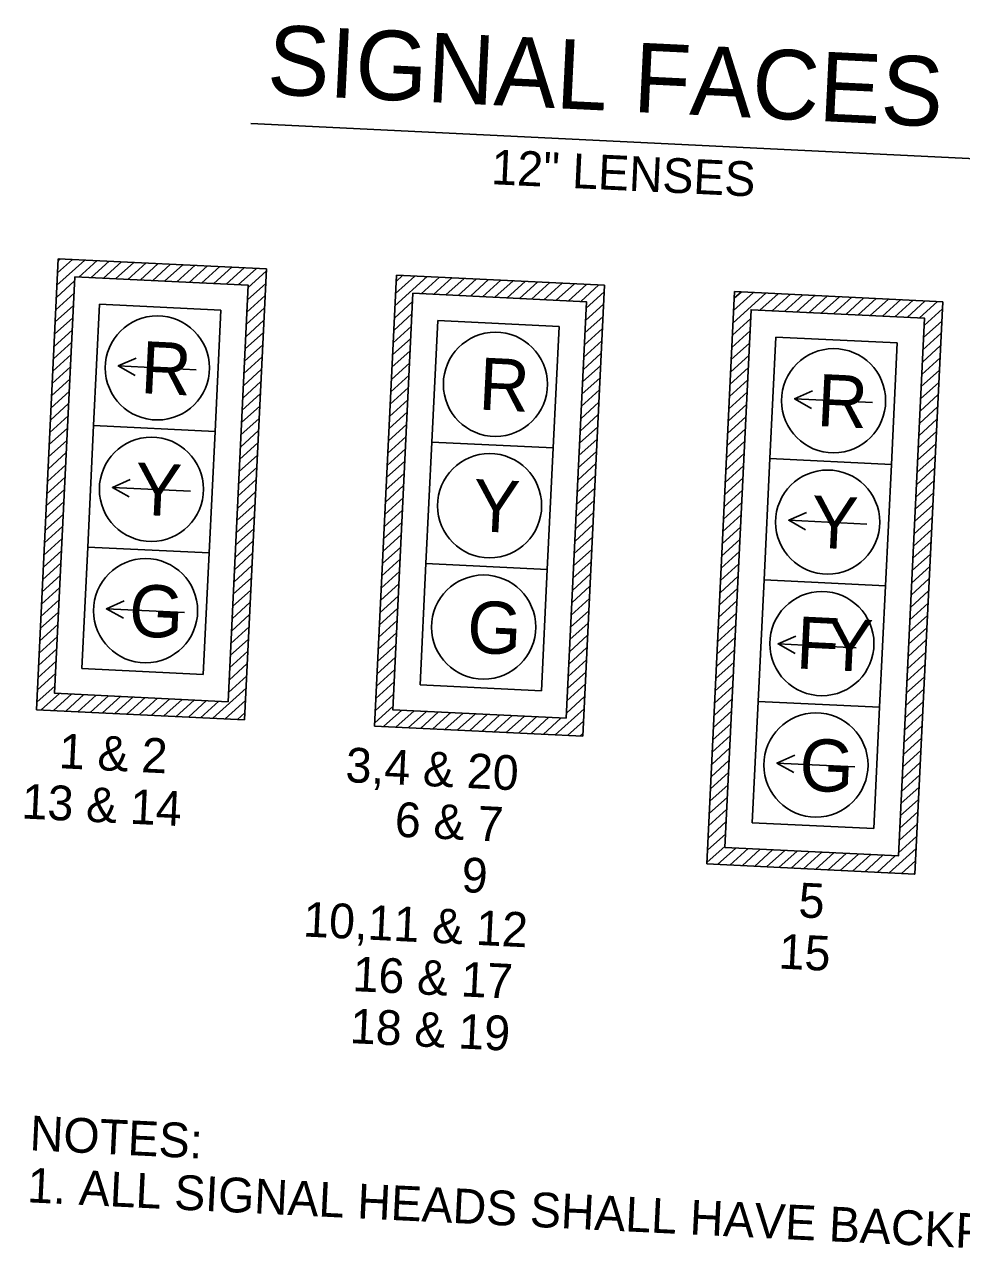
# Model space of a CAD drawing. Extents: x 662220 to 671027, y 641390 to 743815.
# Drawn here: x 662467.9 to 662575.9, y 642595.1 to 642736.9 of the extents above; entities that cross this region are included whole.
import ezdxf

# ---------------------------------------------------------------- set-up
doc = ezdxf.new("R2010")
doc.units = 0
doc.layers.add('R_Proposed Road Annot', color=7, linetype='Continuous')

msp = doc.modelspace()

# ---------------------------------------------------------------- linework, layer by layer
at = {"layer": 'R_Proposed Road Annot'}
for p, q in [((662494.01, 642725.55), (662592.08, 642720.79)), ((662469.3, 642658.04), (662471.82, 642709.98)), ((662471.67, 642706.94), (662474.87, 642709.83)), ((662471.74, 642708.35), (662473.46, 642709.9)), ((662471.81, 642709.76), (662472.04, 642709.97)), ((662471.82, 642709.98), (662495.79, 642708.82)), ((662474.19, 642707.86), (662476.28, 642709.77)), ((662475.6, 642707.8), (662477.69, 642709.7)), ((662477.01, 642707.73), (662479.11, 642709.63)), ((662478.42, 642707.66), (662480.52, 642709.56)), ((662479.84, 642707.59), (662481.93, 642709.49)), ((662481.25, 642707.52), (662483.34, 642709.42)), ((662482.66, 642707.45), (662484.76, 642709.35)), ((662484.07, 642707.38), (662486.17, 642709.28)), ((662485.49, 642707.32), (662487.58, 642709.22)), ((662486.9, 642707.25), (662488.99, 642709.15)), ((662488.31, 642707.18), (662490.41, 642709.08)), ((662489.72, 642707.11), (662491.82, 642709.01)), ((662491.14, 642707.04), (662493.23, 642708.94)), ((662492.55, 642706.97), (662494.64, 642708.87)), ((662495.79, 642708.82), (662493.27, 642656.88)), ((662493.69, 642706.65), (662495.78, 642708.55)), ((662510.78, 642708.09), (662508.25, 642656.15)), ((662510.6, 642704.55), (662514.32, 642707.92)), ((662510.67, 642705.96), (662512.91, 642707.99)), ((662510.74, 642707.37), (662511.49, 642708.06)), ((662534.75, 642706.93), (662510.78, 642708.09)), ((662513.64, 642705.95), (662515.73, 642707.85)), ((662515.05, 642705.88), (662517.14, 642707.78)), ((662516.46, 642705.81), (662518.56, 642707.71)), ((662471.61, 642705.52), (662473.7, 642707.42)), ((662493.62, 642705.24), (662495.71, 642707.14)), ((662517.87, 642705.74), (662519.97, 642707.64)), ((662519.29, 642705.67), (662521.38, 642707.58)), ((662520.7, 642705.61), (662522.79, 642707.51)), ((662522.11, 642705.54), (662524.21, 642707.44)), ((662523.52, 642705.47), (662525.62, 642707.37)), ((662524.94, 642705.4), (662527.03, 642707.3)), ((662526.35, 642705.33), (662528.44, 642707.23)), ((662527.76, 642705.26), (662529.86, 642707.16)), ((662529.17, 642705.19), (662531.27, 642707.09)), ((662530.59, 642705.13), (662532.68, 642707.03)), ((662532, 642705.06), (662534.09, 642706.96)), ((662532.23, 642654.99), (662534.75, 642706.93)), ((662471.54, 642704.11), (662473.63, 642706.01)), ((662493.55, 642703.83), (662495.64, 642705.73)), ((662510.54, 642703.13), (662512.63, 642705.04)), ((662532.62, 642704.27), (662534.71, 642706.17)), ((662546.53, 642640.28), (662549.73, 642706.2)), ((662549.55, 642702.6), (662553.33, 642706.02)), ((662549.62, 642704.01), (662551.92, 642706.09)), ((662549.69, 642705.42), (662550.51, 642706.16)), ((662549.73, 642706.2), (662573.7, 642705.03)), ((662552.65, 642704.05), (662554.75, 642705.95)), ((662554.06, 642703.99), (662556.16, 642705.89)), ((662555.48, 642703.92), (662557.57, 642705.82)), ((662556.89, 642703.85), (662558.98, 642705.75)), ((662558.3, 642703.78), (662560.4, 642705.68)), ((662559.71, 642703.71), (662561.81, 642705.61)), ((662561.13, 642703.64), (662563.22, 642705.54)), ((662562.54, 642703.57), (662564.63, 642705.47)), ((662563.95, 642703.51), (662566.05, 642705.41)), ((662565.36, 642703.44), (662567.46, 642705.34)), ((662566.78, 642703.37), (662568.87, 642705.27)), ((662568.19, 642703.3), (662570.28, 642705.2)), ((662569.6, 642703.23), (662571.7, 642705.13)), ((662573.7, 642705.03), (662570.5, 642639.11)), ((662571.01, 642703.16), (662573.11, 642705.06)), ((662471.47, 642702.7), (662473.56, 642704.6)), ((662476.57, 642704.75), (662475.89, 642690.76)), ((662476.57, 642704.75), (662490.56, 642704.07)), ((662490.56, 642704.07), (662489.88, 642690.08)), ((662493.48, 642702.42), (662495.57, 642704.32)), ((662510.47, 642701.72), (662512.56, 642703.62)), ((662532.55, 642702.85), (662534.64, 642704.75)), ((662571.57, 642702.31), (662573.66, 642704.22)), ((662471.4, 642701.29), (662473.49, 642703.19)), ((662493.41, 642701), (662495.51, 642702.9)), ((662510.4, 642700.31), (662512.49, 642702.21)), ((662515.53, 642702.85), (662514.85, 642688.87)), ((662515.53, 642702.85), (662529.51, 642702.17)), ((662529.51, 642702.17), (662528.83, 642688.19)), ((662532.48, 642701.44), (662534.57, 642703.34)), ((662549.49, 642701.18), (662551.58, 642703.08)), ((662571.5, 642700.9), (662573.59, 642702.8)), ((662471.33, 642699.87), (662473.43, 642701.77)), ((662493.34, 642699.59), (662495.44, 642701.49)), ((662510.33, 642698.9), (662512.42, 642700.8)), ((662532.41, 642700.03), (662534.5, 642701.93)), ((662549.42, 642699.77), (662551.51, 642701.67)), ((662554.48, 642700.96), (662553.8, 642686.98)), ((662554.48, 642700.96), (662568.46, 642700.28)), ((662571.43, 642699.49), (662573.52, 642701.39)), ((662471.26, 642698.46), (662473.36, 642700.36)), ((662493.27, 642698.18), (662495.37, 642700.08)), ((662510.26, 642697.48), (662512.36, 642699.39)), ((662532.34, 642698.62), (662534.44, 642700.52)), ((662549.35, 642698.36), (662551.44, 642700.26)), ((662568.46, 642700.28), (662567.79, 642686.3)), ((662571.36, 642698.08), (662573.46, 642699.98)), ((662471.19, 642697.05), (662473.29, 642698.95)), ((662493.21, 642696.77), (662495.3, 642698.67)), ((662510.19, 642696.07), (662512.29, 642697.97)), ((662532.27, 642697.2), (662534.37, 642699.1)), ((662549.28, 642696.95), (662551.38, 642698.85)), ((662571.29, 642696.66), (662573.39, 642698.56)), ((662471.12, 642695.63), (662473.22, 642697.54)), ((662487.72, 642697.2), (662478.73, 642697.63)), ((662493.14, 642695.35), (662495.23, 642697.25)), ((662510.12, 642694.66), (662512.22, 642696.56)), ((662532.2, 642695.79), (662534.3, 642697.69)), ((662549.21, 642695.53), (662551.31, 642697.43)), ((662571.22, 642695.25), (662573.32, 642697.15)), ((662471.06, 642694.22), (662473.15, 642696.12)), ((662493.07, 642693.94), (662495.16, 642695.84)), ((662510.05, 642693.25), (662512.15, 642695.15)), ((662532.14, 642694.38), (662534.23, 642696.28)), ((662549.14, 642694.12), (662551.24, 642696.02)), ((662571.16, 642693.84), (662573.25, 642695.74)), ((662470.99, 642692.81), (662473.08, 642694.71)), ((662493, 642692.53), (662495.09, 642694.43)), ((662509.99, 642691.83), (662512.08, 642693.74)), ((662532.07, 642692.97), (662534.16, 642694.87)), ((662549.07, 642692.71), (662551.17, 642694.61)), ((662565.63, 642693.41), (662556.64, 642693.85)), ((662571.09, 642692.43), (662573.18, 642694.33)), ((662470.92, 642691.4), (662473.01, 642693.3)), ((662492.93, 642691.12), (662495.03, 642693.02)), ((662509.92, 642690.42), (662512.01, 642692.32)), ((662532, 642691.55), (662534.09, 642693.45)), ((662549.01, 642691.3), (662551.1, 642693.2)), ((662571.02, 642691.01), (662573.11, 642692.91)), ((662470.85, 642689.98), (662472.95, 642691.89)), ((662475.89, 642690.76), (662475.22, 642676.78)), ((662475.89, 642690.76), (662489.88, 642690.08)), ((662492.86, 642689.7), (662494.96, 642691.6)), ((662509.85, 642689.01), (662511.94, 642690.91)), ((662531.93, 642690.14), (662534.02, 642692.04)), ((662548.94, 642689.88), (662551.03, 642691.78)), ((662570.95, 642689.6), (662573.04, 642691.5)), ((662470.78, 642688.57), (662472.88, 642690.47)), ((662489.88, 642690.08), (662489.2, 642676.1)), ((662492.79, 642688.29), (662494.89, 642690.19)), ((662509.78, 642687.6), (662511.88, 642689.5)), ((662531.86, 642688.73), (662533.96, 642690.63)), ((662548.87, 642688.47), (662550.96, 642690.37)), ((662570.88, 642688.19), (662572.98, 642690.09)), ((662470.71, 642687.16), (662472.81, 642689.06)), ((662492.73, 642686.88), (662494.82, 642688.78)), ((662509.71, 642686.18), (662511.81, 642688.08)), ((662514.85, 642688.87), (662514.17, 642674.89)), ((662514.85, 642688.87), (662528.83, 642688.19)), ((662528.83, 642688.19), (662528.15, 642674.21)), ((662531.79, 642687.32), (662533.89, 642689.22)), ((662548.8, 642687.06), (662550.89, 642688.96)), ((662570.81, 642686.78), (662572.91, 642688.68)), ((662470.64, 642685.75), (662472.74, 642687.65)), ((662492.66, 642685.47), (662494.75, 642687.37)), ((662509.64, 642684.77), (662511.74, 642686.67)), ((662531.72, 642685.9), (662533.82, 642687.8)), ((662548.73, 642685.65), (662550.83, 642687.55)), ((662553.8, 642686.98), (662553.12, 642672.99)), ((662553.8, 642686.98), (662567.79, 642686.3)), ((662570.74, 642685.36), (662572.84, 642687.26)), ((662470.58, 642684.33), (662472.67, 642686.24)), ((662492.59, 642684.05), (662494.68, 642685.95)), ((662509.57, 642683.36), (662511.67, 642685.26)), ((662531.66, 642684.49), (662533.75, 642686.39)), ((662548.66, 642684.23), (662550.76, 642686.13)), ((662567.79, 642686.3), (662567.11, 642672.32)), ((662570.68, 642683.95), (662572.77, 642685.85)), ((662470.51, 642682.92), (662472.6, 642684.82)), ((662487.04, 642683.21), (662478.05, 642683.65)), ((662492.52, 642682.64), (662494.61, 642684.54)), ((662509.51, 642681.95), (662511.6, 642683.85)), ((662531.59, 642683.08), (662533.68, 642684.98)), ((662548.59, 642682.82), (662550.69, 642684.72)), ((662570.61, 642682.54), (662572.7, 642684.44)), ((662470.44, 642681.51), (662472.53, 642683.41)), ((662492.45, 642681.23), (662494.55, 642683.13)), ((662509.44, 642680.53), (662511.53, 642682.43)), ((662531.52, 642681.67), (662533.61, 642683.57)), ((662548.53, 642681.41), (662550.62, 642683.31)), ((662570.54, 642681.13), (662572.63, 642683.03)), ((662470.37, 642680.1), (662472.47, 642682)), ((662492.38, 642679.82), (662494.48, 642681.72)), ((662509.37, 642679.12), (662511.46, 642681.02)), ((662531.45, 642680.25), (662533.54, 642682.15)), ((662548.46, 642679.99), (662550.55, 642681.9)), ((662570.47, 642679.71), (662572.56, 642681.61)), ((662470.3, 642678.68), (662472.4, 642680.58)), ((662492.31, 642678.4), (662494.41, 642680.3)), ((662509.3, 642677.71), (662511.4, 642679.61)), ((662531.38, 642678.84), (662533.48, 642680.74)), ((662548.39, 642678.58), (662550.48, 642680.48)), ((662564.95, 642679.43), (662555.96, 642679.87)), ((662570.4, 642678.3), (662572.5, 642680.2)), ((662470.23, 642677.27), (662472.33, 642679.17)), ((662492.25, 642676.99), (662494.34, 642678.89)), ((662509.23, 642676.3), (662511.33, 642678.2)), ((662531.31, 642677.43), (662533.41, 642679.33)), ((662548.32, 642677.17), (662550.41, 642679.07)), ((662570.33, 642676.89), (662572.43, 642678.79)), ((662470.16, 642675.86), (662472.26, 642677.76)), ((662475.22, 642676.78), (662474.54, 642662.79)), ((662475.22, 642676.78), (662489.2, 642676.1)), ((662492.18, 642675.58), (662494.27, 642677.48)), ((662509.16, 642674.88), (662511.26, 642676.78)), ((662531.18, 642674.6), (662533.27, 642676.5)), ((662531.24, 642676.02), (662533.34, 642677.92)), ((662548.25, 642675.76), (662550.35, 642677.66)), ((662570.26, 642675.48), (662572.36, 642677.38)), ((662470.1, 642674.45), (662472.19, 642676.35)), ((662489.2, 642676.1), (662488.52, 642662.12)), ((662492.11, 642674.17), (662494.2, 642676.07)), ((662509.09, 642673.47), (662511.19, 642675.37)), ((662531.11, 642673.19), (662533.2, 642675.09)), ((662548.18, 642674.34), (662550.28, 642676.25)), ((662570.2, 642674.06), (662572.29, 642675.96)), ((662470.03, 642673.03), (662472.12, 642674.93)), ((662492.04, 642672.75), (662494.13, 642674.65)), ((662509.03, 642672.06), (662511.12, 642673.96)), ((662514.17, 642674.89), (662513.49, 642660.9)), ((662514.17, 642674.89), (662528.15, 642674.21)), ((662528.15, 642674.21), (662527.47, 642660.22)), ((662531.04, 642671.78), (662533.13, 642673.68)), ((662548.11, 642672.93), (662550.21, 642674.83)), ((662570.13, 642672.65), (662572.22, 642674.55)), ((662469.96, 642671.62), (662472.05, 642673.52)), ((662491.97, 642671.34), (662494.07, 642673.24)), ((662508.96, 642670.65), (662511.05, 642672.55)), ((662530.97, 642670.37), (662533.06, 642672.27)), ((662548.05, 642671.52), (662550.14, 642673.42)), ((662553.12, 642672.99), (662552.44, 642659.01)), ((662553.12, 642672.99), (662567.11, 642672.32)), ((662567.11, 642672.32), (662566.43, 642658.33)), ((662570.06, 642671.24), (662572.15, 642673.14)), ((662469.89, 642670.21), (662471.98, 642672.11)), ((662491.9, 642669.93), (662494, 642671.83)), ((662508.89, 642669.23), (662510.98, 642671.13)), ((662530.9, 642668.95), (662533, 642670.85)), ((662547.98, 642670.11), (662550.07, 642672.01)), ((662569.99, 642669.83), (662572.08, 642671.73)), ((662469.82, 642668.8), (662471.92, 642670.7)), ((662486.36, 642669.23), (662477.37, 642669.66)), ((662491.83, 642668.52), (662493.93, 642670.42)), ((662508.82, 642667.82), (662510.91, 642669.72)), ((662530.83, 642667.54), (662532.93, 642669.44)), ((662547.91, 642668.69), (662550, 642670.6)), ((662569.92, 642668.41), (662572.02, 642670.31)), ((662469.75, 642667.38), (662471.85, 642669.28)), ((662491.77, 642667.1), (662493.86, 642669)), ((662508.75, 642666.41), (662510.85, 642668.31)), ((662530.76, 642666.13), (662532.86, 642668.03)), ((662547.84, 642667.28), (662549.93, 642669.18)), ((662569.85, 642667), (662571.95, 642668.9)), ((662469.68, 642665.97), (662471.78, 642667.87)), ((662491.7, 642665.69), (662493.79, 642667.59)), ((662508.68, 642665), (662510.78, 642666.9)), ((662530.7, 642664.71), (662532.79, 642666.62)), ((662547.77, 642665.87), (662549.87, 642667.77)), ((662569.78, 642665.59), (662571.88, 642667.49)), ((662469.62, 642664.56), (662471.71, 642666.46)), ((662491.63, 642664.28), (662493.72, 642666.18)), ((662508.61, 642663.58), (662510.71, 642665.48)), ((662530.63, 642663.3), (662532.72, 642665.2)), ((662547.7, 642664.46), (662549.8, 642666.36)), ((662563.73, 642665.19), (662554.74, 642665.63)), ((662569.72, 642664.18), (662571.81, 642666.08)), ((662469.55, 642663.15), (662471.64, 642665.05)), ((662491.56, 642662.87), (662493.65, 642664.77)), ((662508.55, 642662.17), (662510.64, 642664.07)), ((662530.56, 642661.89), (662532.65, 642663.79)), ((662547.63, 642663.04), (662549.73, 642664.94)), ((662569.65, 642662.76), (662571.74, 642664.66)), ((662469.48, 642661.73), (662471.57, 642663.63)), ((662474.54, 642662.79), (662488.52, 642662.12)), ((662491.49, 642661.45), (662493.59, 642663.35)), ((662508.48, 642660.76), (662510.57, 642662.66)), ((662530.49, 642660.48), (662532.58, 642662.38)), ((662547.57, 642661.63), (662549.66, 642663.53)), ((662569.58, 642661.35), (662571.67, 642663.25)), ((662469.41, 642660.32), (662471.5, 642662.22)), ((662491.42, 642660.04), (662493.52, 642661.94)), ((662508.41, 642659.35), (662510.5, 642661.25)), ((662513.49, 642660.9), (662527.47, 642660.22)), ((662530.42, 642659.06), (662532.52, 642660.97)), ((662547.5, 642660.22), (662549.59, 642662.12)), ((662569.51, 642659.94), (662571.6, 642661.84)), ((662469.34, 642658.91), (662471.44, 642660.81)), ((662469.85, 642658.02), (662471.94, 642659.92)), ((662471.26, 642657.95), (662473.35, 642659.85)), ((662472.67, 642657.88), (662474.77, 642659.78)), ((662474.08, 642657.81), (662476.18, 642659.71)), ((662475.5, 642657.74), (662477.59, 642659.64)), ((662476.91, 642657.67), (662479, 642659.57)), ((662478.32, 642657.6), (662480.42, 642659.51)), ((662489.62, 642657.06), (662493.45, 642660.53)), ((662508.34, 642657.93), (662510.43, 642659.83)), ((662530.35, 642657.65), (662532.45, 642659.55)), ((662547.43, 642658.81), (662549.52, 642660.71)), ((662569.44, 642658.53), (662571.54, 642660.43)), ((662479.73, 642657.54), (662481.83, 642659.44)), ((662481.15, 642657.47), (662483.24, 642659.37)), ((662482.56, 642657.4), (662484.65, 642659.3)), ((662483.97, 642657.33), (662486.07, 642659.23)), ((662485.38, 642657.26), (662487.48, 642659.16)), ((662486.8, 642657.19), (662488.89, 642659.09)), ((662488.21, 642657.12), (662490.3, 642659.03)), ((662491.03, 642656.99), (662493.38, 642659.12)), ((662508.27, 642656.52), (662510.37, 642658.42)), ((662529.07, 642655.14), (662532.38, 642658.14)), ((662547.36, 642657.39), (662549.45, 642659.29)), ((662552.44, 642659.01), (662551.77, 642645.03)), ((662552.44, 642659.01), (662566.43, 642658.33)), ((662566.43, 642658.33), (662565.75, 642644.35)), ((662569.37, 642657.11), (662571.47, 642659.01)), ((662493.27, 642656.88), (662469.3, 642658.04)), ((662492.45, 642656.92), (662493.31, 642657.7)), ((662509.3, 642656.1), (662511.39, 642658)), ((662510.71, 642656.03), (662512.8, 642657.93)), ((662512.12, 642655.96), (662514.22, 642657.86)), ((662513.53, 642655.89), (662515.63, 642657.8)), ((662514.95, 642655.83), (662517.04, 642657.73)), ((662516.36, 642655.76), (662518.45, 642657.66)), ((662517.77, 642655.69), (662519.87, 642657.59)), ((662519.18, 642655.62), (662521.28, 642657.52)), ((662520.6, 642655.55), (662522.69, 642657.45)), ((662522.01, 642655.48), (662524.1, 642657.38)), ((662523.42, 642655.41), (662525.52, 642657.32)), ((662524.83, 642655.35), (662526.93, 642657.25)), ((662526.25, 642655.28), (662528.34, 642657.18)), ((662527.66, 642655.21), (662529.75, 642657.11)), ((662530.48, 642655.07), (662532.31, 642656.73)), ((662547.29, 642655.98), (662549.39, 642657.88)), ((662569.3, 642655.7), (662571.4, 642657.6)), ((662508.25, 642656.15), (662532.23, 642654.99)), ((662531.9, 642655), (662532.24, 642655.32)), ((662547.22, 642654.57), (662549.32, 642656.47)), ((662569.23, 642654.29), (662571.33, 642656.19)), ((662547.15, 642653.16), (662549.25, 642655.06)), ((662569.17, 642652.88), (662571.26, 642654.78)), ((662547.09, 642651.74), (662549.18, 642653.64)), ((662569.1, 642651.46), (662571.19, 642653.36)), ((662547.02, 642650.33), (662549.11, 642652.23)), ((662563.59, 642651.46), (662554.6, 642651.9)), ((662569.03, 642650.05), (662571.12, 642651.95)), ((662546.95, 642648.92), (662549.04, 642650.82)), ((662568.96, 642648.64), (662571.06, 642650.54)), ((662546.88, 642647.51), (662548.97, 642649.41)), ((662568.89, 642647.23), (662570.99, 642649.13)), ((662546.81, 642646.09), (662548.91, 642647.99)), ((662568.82, 642645.81), (662570.92, 642647.71)), ((662546.74, 642644.68), (662548.84, 642646.58)), ((662568.75, 642644.4), (662570.85, 642646.3)), ((662546.67, 642643.27), (662548.77, 642645.17)), ((662551.77, 642645.03), (662565.75, 642644.35)), ((662568.69, 642642.99), (662570.78, 642644.89)), ((662546.61, 642641.86), (662548.7, 642643.76)), ((662568.62, 642641.57), (662570.71, 642643.48)), ((662546.54, 642640.44), (662548.63, 642642.34)), ((662547.77, 642640.22), (662549.87, 642642.12)), ((662549.19, 642640.15), (662551.28, 642642.05)), ((662550.6, 642640.08), (662552.69, 642641.98)), ((662552.01, 642640.01), (662554.11, 642641.91)), ((662553.42, 642639.94), (662555.52, 642641.84)), ((662554.84, 642639.87), (662556.93, 642641.77)), ((662556.25, 642639.8), (662558.34, 642641.7)), ((662557.66, 642639.74), (662559.76, 642641.64)), ((662559.07, 642639.67), (662561.17, 642641.57)), ((662560.49, 642639.6), (662562.58, 642641.5)), ((662561.9, 642639.53), (662563.99, 642641.43)), ((662563.31, 642639.46), (662565.41, 642641.36)), ((662564.72, 642639.39), (662566.82, 642641.29)), ((662566.14, 642639.32), (662568.23, 642641.22)), ((662567.55, 642639.26), (662570.64, 642642.06)), ((662570.5, 642639.11), (662546.53, 642640.28)), ((662568.96, 642639.19), (662570.58, 642640.65)), ((662570.37, 642639.12), (662570.51, 642639.24))]:
    msp.add_line(p, q, dxfattribs=at)
for points in [[(662473.72, 642707.89), (662493.7, 642706.92), (662491.37, 642658.97), (662471.39, 642659.94)], [(662530.32, 642657.08), (662532.65, 642705.03), (662512.68, 642706), (662510.35, 642658.05)], [(662548.62, 642642.18), (662551.63, 642704.1), (662571.61, 642703.13), (662568.6, 642641.21)]]:
    msp.add_lwpolyline(points, close=True, dxfattribs=at)
for points in [[(662480.78, 642698.53), (662478.73, 642697.63), (662480.68, 642696.54)], [(662558.69, 642694.75), (662556.64, 642693.85), (662558.59, 642692.75)], [(662480.1, 642684.55), (662478.05, 642683.65), (662480, 642682.55)], [(662558.01, 642680.77), (662555.96, 642679.87), (662557.91, 642678.77)], [(662479.42, 642670.57), (662477.37, 642669.66), (662479.32, 642668.57)], [(662556.79, 642666.53), (662554.74, 642665.63), (662556.69, 642664.53)], [(662556.65, 642652.8), (662554.6, 642651.9), (662556.55, 642650.8)]]:
    msp.add_lwpolyline(points, dxfattribs=at)
for centre in [(662483.23, 642697.41), (662522.18, 642695.52), (662561.13, 642693.63), (662482.55, 642683.43), (662521.5, 642681.54), (662560.45, 642679.65), (662481.87, 642669.45), (662520.82, 642667.56), (662559.78, 642665.66), (662559.1, 642651.68)]:
    msp.add_circle(centre, 6, dxfattribs=at)

# ---------------------------------------------------------------- texts
for s, height, rotation, p in [('SIGNAL FACES', 8, 357.2199, (662495.78, 642728.94)), ('12" LENSES', 4, 357.2919, (662521.63, 642718.57)), ('R', 6, 357.2199, (662481.22, 642694.51)), ('R', 6, 357.2199, (662520.17, 642692.62)), ('R', 6, 357.2199, (662559.13, 642690.73)), ('Y', 6, 357.2199, (662480.51, 642680.53)), ('Y', 6, 357.2199, (662519.47, 642678.63)), ('Y', 6, 357.2199, (662558.42, 642676.74)), ('G', 6, 357.2199, (662479.86, 642666.54)), ('G', 6, 357.2199, (662518.81, 642664.65)), ('F', 6, 357.2199, (662556.73, 642662.81)), ('Y', 6, 357.2199, (662560.15, 642662.64)), ('1 & 2', 4, 357.2199, (662471.82, 642651.32)), ('G', 6, 357.2199, (662557.09, 642648.78)), ('3,4 & 20', 4, 357.2199, (662504.85, 642649.72)), ('13 & 14', 4, 357.2199, (662467.53, 642645.53)), ('6 & 7', 4, 357.2199, (662510.52, 642643.44)), ('9', 4, 357.2199, (662518.21, 642637.06)), ('5', 4, 357.2199, (662557.03, 642634.15)), ('10,11 & 12', 4, 357.2199, (662499.96, 642631.94)), ('15', 4, 357.2199, (662554.74, 642628.25)), ('16 & 17', 4, 357.2199, (662505.65, 642625.65)), ('18 & 19', 4, 357.2199, (662505.35, 642619.66)), ('NOTES:', 4, 357.2199, (662468.47, 642607.32)), ('1. ALL SIGNAL HEADS SHALL HAVE BACKPLATES.', 4, 357.2199, (662468.18, 642601.33))]:
    msp.add_text(s, height=height, rotation=rotation, dxfattribs=at).set_placement(p)

doc.saveas('drawing.dxf')
